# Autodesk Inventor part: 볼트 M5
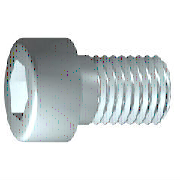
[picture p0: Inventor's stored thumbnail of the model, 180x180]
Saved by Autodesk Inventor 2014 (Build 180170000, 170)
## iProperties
IsCustomPart: 1
Created: 2012-02
Part Number: 볼트 M5
Material: 강철, 연강
Description: 6각머리 태핑 나사
Document SubType Name: Modeling
Standard: KS B 1003
Designer: mduedu
Standards Organization: KS
Language: ko-KR
Size Designation: M 5 x 12
Categories: <MemberInstance><Categories><Category DisplayName="조임쇠" InternalName="e4da775c-781d-43d5-af7c-5136215cf5a6" Mnemonic="FSTN"><Category DisplayName="볼트" InternalN
Density: 1 g/cm^3
Appearance: 강철
Author: mduedu
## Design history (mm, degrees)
sketch "스케치1"
  geometry: L1 (-1.167, 0)-(12, 0); L2 (12, 0)-(12, 2.5); L3 (12, 2.5)-(2, 2.5); L4 (2, 2.5)-(1.509, 2.5); L5 (1.509, 2.5)-(0, 2.5); L6 (0, 2.5)-(0, 4.25); L7 (0, 4.25)-(-5, 4.25); L8 (-5, 4.25)-(-5, 2.309); L9 (-5, 2.309)-(-2.5, 2.309); L10 (-2.5, 2.309)-(-1.167, 0); L11 (-8.4, 0)-(15.4, 0) reference; L12 (0, -0.85)-(0, 5.1) reference; L13 (2, 2.5)-(0, 2.5)
  constraints: 22 end point, 6 parallel, 2 collinear, 2 perpendicular, 1 horizontal, 1 point on line
  dimensions: "d1" = 10 distance from line of L3.end L2 (= GEL); "d2" = 0.49086 distance of L4.end L3.end (computed from GAL); "d3" = 5 distance between parallel lines of L8 L6 (= KOH); "d4" = 2.5 distance of L8.end L9.end (= INTI); "d5" = 60 deg angle of L10 L1; "d6" = 5 diameter of L3 L1 (= GD); "d7" = 5 diameter of L5 L1 (= BDM); "d8" = 4.6188 diameter of L9 L1 (= 1.1547 x SW); "d9" = 8.5 diameter of L7 L1 (= KOD); "d26" = 12 distance between parallel lines of L12 L2 (= NLG)
revolve "본체" sketch "스케치1" stored, may be unused: angle "d10" = 90 deg
sketch "스케치2"
  geometry: L1 (0, -5.95)-(0, 5.95) reference; L2 (-5.95, 0)-(5.95, 0) reference; L3 (2.309, 0)-(1.155, -2); L4 (1.155, -2)-(-1.155, -2); L5 (-1.155, -2)-(-2.309, 0); L6 (-2.309, 0)-(-1.155, 2); L7 (-1.155, 2)-(1.155, 2); L8 (1.155, 2)-(2.309, 0); 2 further points
  constraints: 12 end point, 1 coincident, 1 horizontal alignment, 1 point on line, 12 other
extrude "슬롯" join sketch "스케치2" stored distance "d11" = 10; taper "d12" = 0 deg
workplane "Work Plane1"
fillet "Fillet2" dims "d30" = 0.1 (= R)
body "Solid1"
fillet "모깎기1" dims "d17" = 0.5 (= RR)
feature "스레드" dims "d13" = 10 (= GEL), "d14" = 0
chamfer "모따기1" distance "d15" = 0.49076 (= -0.5 x SPD + 0.5 x GD); stored, may be unused: second distance "d16" = 0.49076 (= GUL), angle "d27" = 45 deg
other parameters: "GD" = 5 (= NND) [user parameter; used in 2 equation terms], "NLG" = 12 [user parameter; used in 1 equation term], "GEL" = 10 [user parameter; used in 2 equation terms], "KOD" = 8.5 [user parameter; used in 1 equation term], "KOH" = 5 [user parameter; used in 1 equation term], "INTI" = 2.5 [user parameter; used in 1 equation term], "GAL" = 0.49076 (= 0.61345 x PTC) [user parameter; used in 1 equation term], "GUL" = 0.49076 (= 0.61345 x PTC) [user parameter; used in 1 equation term], "BDM" = 5 (= NND) [user parameter; used in 1 equation term], "SW" = 4 [user parameter; used in 2 equation terms], "RR" = 0.5 [user parameter; used in 1 equation term], "SPD" = 4.01848 (= NND - 1.2269 x PTC) [user parameter; used in 1 equation term], "d19" = 0, "d28" = 0, "d29" = 0, "R" = 0.1 [user parameter; used in 1 equation term], "PHH" = 0.2 [user parameter], "GD1" = 4.01848 (= THREADDIA - 1.2269 x PTC) [user parameter], "THREADDIA" = 5 [user parameter; used in 1 equation term], "FAWI" = 45 deg [user parameter], "TPU" = 12.5 (computed from PTC) [user parameter], "PTC" = 0.8 [user parameter; used in 5 equation terms], "NND" = 5 [user parameter; used in 3 equation terms], "TOA" = 30 deg [user parameter], "E0" = 4.62 (= 1.155 x SW) [user parameter]
